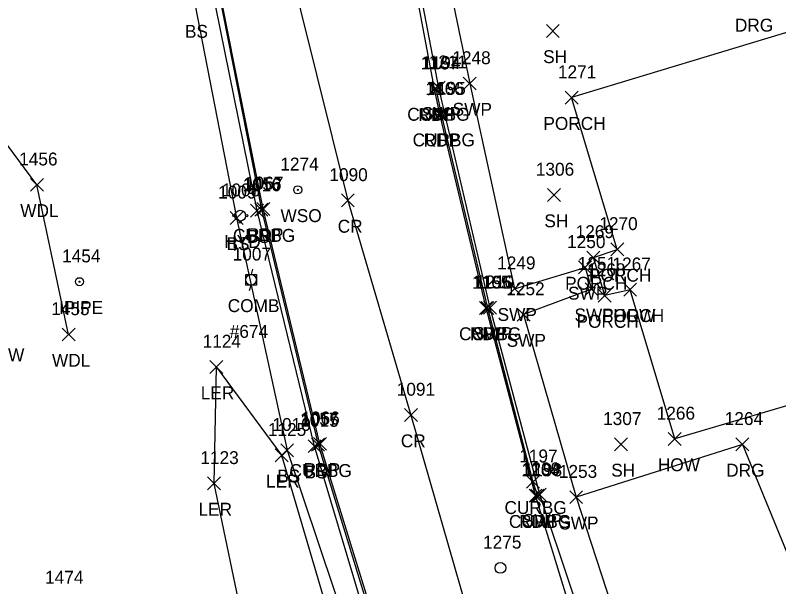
# Model space of a CAD drawing. Extents: x 462930 to 463548, y 29607 to 30453.
# Drawn here: x 463327.91 to 463364, y 30004.79 to 30031.8 of the extents above; entities that cross this region are included whole.
import ezdxf

# ---------------------------------------------------------------- set-up
doc = ezdxf.new("R2010")
doc.units = 0
for name, color, linetype in [('L_A', 7, 'Continuous'), ('L_I', 7, 'Continuous'), ('L_TIC', 7, 'Continuous'), ('LARO', 7, 'Continuous'), ('LAWA', 7, 'Continuous'), ('LBC', 7, 'Continuous'), ('LBF', 7, 'Continuous'), ('LELB', 7, 'Continuous'), ('M_A', 7, 'Continuous'), ('M_I', 7, 'Continuous'), ('MPIP', 7, 'Continuous'), ('P_A', 7, 'Continuous'), ('P_I', 7, 'Continuous'), ('P_TIC', 7, 'Continuous'), ('PET', 7, 'Continuous'), ('PRC', 7, 'Continuous'), ('R_A', 7, 'Continuous'), ('R_I', 7, 'Continuous'), ('R_TIC', 7, 'Continuous'), ('RC', 7, 'Continuous'), ('RDG', 7, 'Continuous'), ('RSW', 7, 'Continuous'), ('U_A', 7, 'Continuous'), ('U_C', 7, 'Continuous'), ('U_I', 7, 'Continuous'), ('UP', 7, 'Continuous'), ('UUMH', 7, 'Continuous'), ('UWFH', 7, 'Continuous'), ('UWV', 7, 'Continuous')]:
    doc.layers.add(name, color=color, linetype=linetype)

msp = doc.modelspace()

# ---------------------------------------------------------------- linework, layer by layer
at = {"layer": 'L_TIC'}
for points in [[(463353.022, 30030.753), (463353.632, 30031.363)], [(463353.632, 30030.753), (463353.022, 30031.363)], [(463353.908, 30027.599), (463354.518, 30028.209)], [(463354.518, 30027.599), (463353.908, 30028.209)], [(463328.628, 30023.48), (463329.238, 30024.09)], [(463329.238, 30023.48), (463328.628, 30024.09)], [(463353.078, 30022.996), (463353.688, 30023.606)], [(463353.688, 30022.996), (463353.078, 30023.606)], [(463339.039, 30022.26), (463339.649, 30022.87)], [(463339.649, 30022.26), (463339.039, 30022.87)], [(463338.068, 30021.915), (463338.678, 30022.525)], [(463338.678, 30021.915), (463338.068, 30022.525)], [(463356.064, 30020.426), (463356.674, 30021.036)], [(463356.674, 30020.426), (463356.064, 30021.036)], [(463354.935, 30020.045), (463355.545, 30020.655)], [(463355.545, 30020.045), (463354.935, 30020.655)], [(463356.675, 30018.519), (463357.285, 30019.129)], [(463357.285, 30018.519), (463356.675, 30019.129)], [(463356.675, 30018.519), (463357.285, 30019.129)], [(463357.285, 30018.519), (463356.675, 30019.129)], [(463355.473, 30018.246), (463356.083, 30018.856)], [(463356.083, 30018.246), (463355.473, 30018.856)], [(463330.127, 30016.406), (463330.737, 30017.016)], [(463330.737, 30016.406), (463330.127, 30017.016)], [(463337.112, 30014.868), (463337.722, 30015.478)], [(463337.722, 30014.868), (463337.112, 30015.478)], [(463341.758, 30011.13), (463342.368, 30011.74)], [(463342.368, 30011.13), (463341.758, 30011.74)], [(463356.241, 30011.213), (463356.851, 30011.823)], [(463356.851, 30011.213), (463356.241, 30011.823)], [(463358.781, 30011.469), (463359.391, 30012.079)], [(463359.391, 30011.469), (463358.781, 30012.079)], [(463340.462, 30010.935), (463341.072, 30011.545)], [(463341.072, 30010.935), (463340.462, 30011.545)], [(463340.197, 30010.697), (463340.807, 30011.307)], [(463340.807, 30010.697), (463340.197, 30011.307)], [(463337.004, 30009.368), (463337.614, 30009.978)], [(463337.614, 30009.368), (463337.004, 30009.978)]]:
    msp.add_lwpolyline(points, dxfattribs=at)
at = {"layer": 'LARO'}
msp.add_lwpolyline([(463338.843, 30002.341), (463337.309, 30009.673), (463337.417, 30015.173), (463340.502, 30011.002), (463343.497, 30000.853), (463342.386, 29996.619)], dxfattribs=at)
at = {"layer": 'LAWA'}
msp.add_lwpolyline([(463330.432, 30016.711), (463328.933, 30023.785), (463324.352, 30029.963), (463323.999, 30045.998), (463316.369, 30054.308), (463309.597, 30050.547)], dxfattribs=at)
at = {"layer": 'LBC'}
for points in [[(463364.851, 30031.129), (463354.213, 30027.904)], [(463359.086, 30011.774), (463356.98, 30018.824)], [(463369.71, 30014.92), (463359.086, 30011.774)]]:
    msp.add_lwpolyline(points, dxfattribs=at)
at = {"layer": 'LBF'}
msp.add_lwpolyline([(463356.98, 30018.824), (463355.778, 30018.551), (463355.24, 30020.35), (463356.369, 30020.731), (463354.213, 30027.904)], dxfattribs=at)
at = {"layer": 'LELB'}
for points in [[(463338.373, 30022.22), (463340.767, 30011.24), (463345.965, 29995.767), (463346.937, 29987.36), (463347.521, 29987.525), (463346.646, 29996.093), (463342.063, 30011.435), (463339.344, 30022.565), (463336.301, 30037.573), (463333.414, 30053.384), (463330.633, 30068.275), (463328.629, 30079.728), (463328.086, 30089.487), (463328.627, 30097.184), (463330.299, 30105.361), (463329.682, 30105.522), (463327.994, 30097.289)], [(463336.408, 30032.254), (463338.373, 30022.22)]]:
    msp.add_lwpolyline(points, dxfattribs=at)
at = {"layer": 'MPIP'}
for radius in [0.191, 0.0254]:
    msp.add_circle((463330.946, 30019.205), radius, dxfattribs=at)
at = {"layer": 'P_TIC'}
for points in [[(463347.428, 30028.015), (463348.038, 30028.625)], [(463348.038, 30028.015), (463347.428, 30028.625)], [(463347.675, 30026.81), (463348.285, 30027.42)], [(463348.285, 30026.81), (463347.675, 30027.42)], [(463343.327, 30022.74), (463343.937, 30023.35)], [(463343.937, 30022.74), (463343.327, 30023.35)], [(463339.328, 30022.341), (463339.938, 30022.951)], [(463339.938, 30022.341), (463339.328, 30022.951)], [(463349.862, 30017.661), (463350.472, 30018.271)], [(463350.472, 30017.661), (463349.862, 30018.271)], [(463346.312, 30012.599), (463346.922, 30013.209)], [(463346.922, 30012.599), (463346.312, 30013.209)], [(463342.009, 30011.241), (463342.619, 30011.851)], [(463342.619, 30011.241), (463342.009, 30011.851)], [(463352.2, 30008.793), (463352.81, 30009.403)], [(463352.81, 30008.793), (463352.2, 30009.403)]]:
    msp.add_lwpolyline(points, dxfattribs=at)
at = {"layer": 'PET'}
for points in [[(463374.338, 29956.391), (463367.555, 29969.533), (463365.556, 29974.625), (463364.583, 29976.896), (463356.695, 29995.475), (463352.505, 30009.098), (463350.167, 30017.966), (463347.98, 30027.115), (463347.733, 30028.32), (463346.051, 30037.294), (463343.907, 30048.483), (463342.761, 30054.643), (463342.551, 30055.85), (463341.301, 30062.483), (463338.432, 30077.399), (463338.227, 30078.623), (463337.48, 30086.968), (463337.479, 30088.196), (463338.474, 30099.226), (463339.751, 30104.374), (463341.961, 30110.783)], [(463349.052, 29990.82), (463346.99, 29996.409), (463342.314, 30011.546), (463339.633, 30022.646), (463336.631, 30037.644), (463333.669, 30053.397), (463330.887, 30068.339), (463328.89, 30079.76), (463328.357, 30089.522), (463328.892, 30097.183), (463330.561, 30105.3)]]:
    msp.add_lwpolyline(points, dxfattribs=at)
at = {"layer": 'PRC'}
msp.add_lwpolyline([(463337.978, 30112.385), (463335.087, 30099.771), (463333.576, 30084.385), (463334.686, 30068.796), (463337.03, 30053.748), (463339.908, 30038.01), (463343.632, 30023.045), (463346.617, 30012.904), (463351.044, 29997.524), (463354.76, 29987.177), (463360.584, 29974.202), (463367.548, 29960.534), (463374.695, 29948.349)], dxfattribs=at)
at = {"layer": 'R_TIC'}
for points in [[(463349.089, 30028.266), (463349.699, 30028.876)], [(463349.699, 30028.266), (463349.089, 30028.876)], [(463347.483, 30028.03), (463348.093, 30028.64)], [(463348.093, 30028.03), (463347.483, 30028.64)], [(463347.625, 30028.066), (463348.235, 30028.676)], [(463348.235, 30028.066), (463347.625, 30028.676)], [(463347.737, 30026.821), (463348.347, 30027.431)], [(463348.347, 30026.821), (463347.737, 30027.431)], [(463339.243, 30022.308), (463339.853, 30022.918)], [(463339.853, 30022.308), (463339.243, 30022.918)], [(463354.542, 30019.576), (463355.152, 30020.186)], [(463355.152, 30019.576), (463354.542, 30020.186)], [(463351.211, 30018.569), (463351.821, 30019.179)], [(463351.821, 30018.569), (463351.211, 30019.179)], [(463354.847, 30018.546), (463355.457, 30019.156)], [(463355.457, 30018.546), (463354.847, 30019.156)], [(463349.932, 30017.659), (463350.542, 30018.269)], [(463350.542, 30017.659), (463349.932, 30018.269)], [(463350.052, 30017.672), (463350.662, 30018.282)], [(463350.662, 30017.672), (463350.052, 30018.282)], [(463351.64, 30017.348), (463352.25, 30017.958)], [(463352.25, 30017.348), (463351.64, 30017.958)], [(463341.919, 30011.196), (463342.529, 30011.806)], [(463342.529, 30011.196), (463341.919, 30011.806)], [(463361.982, 30011.214), (463362.592, 30011.824)], [(463362.592, 30011.214), (463361.982, 30011.824)], [(463352.08, 30009.445), (463352.69, 30010.055)], [(463352.69, 30009.445), (463352.08, 30010.055)], [(463352.29, 30008.789), (463352.9, 30009.399)], [(463352.9, 30008.789), (463352.29, 30009.399)], [(463352.406, 30008.837), (463353.016, 30009.447)], [(463353.016, 30008.837), (463352.406, 30009.447)], [(463354.125, 30008.717), (463354.735, 30009.327)], [(463354.735, 30008.717), (463354.125, 30009.327)]]:
    msp.add_lwpolyline(points, dxfattribs=at)
at = {"layer": 'RC'}
for points in [[(463330.433, 30105.335), (463330.506, 30105.311), (463328.851, 30097.179), (463328.319, 30089.513), (463328.85, 30079.744), (463330.845, 30068.328), (463333.629, 30053.397), (463336.583, 30037.649), (463339.548, 30022.613), (463342.224, 30011.501), (463346.871, 29996.398), (463346.791, 29996.353)], [(463347.788, 30028.335), (463348.042, 30027.126), (463350.237, 30017.964), (463352.385, 30009.75), (463352.595, 30009.094)]]:
    msp.add_lwpolyline(points, dxfattribs=at)
at = {"layer": 'RDG'}
for points in [[(463362.287, 30011.519), (463354.43, 30009.022)], [(463362.287, 30011.519), (463366.742, 30000.689)]]:
    msp.add_lwpolyline(points, dxfattribs=at)
at = {"layer": 'RSW'}
for points in [[(463374.235, 29956.952), (463367.745, 29969.631), (463365.689, 29974.684), (463364.801, 29976.975), (463360.584, 29986.798), (463357.266, 29995.548), (463352.711, 30009.142), (463350.357, 30017.977), (463347.93, 30028.371), (463346.21, 30037.33), (463344.933, 30043.874), (463342.934, 30054.68), (463342.697, 30055.906), (463341.529, 30062.506)], [(463343.219, 30061.394), (463344.068, 30056.729), (463345.278, 30049.664), (463349.011, 30050.331), (463349.136, 30049.5), (463345.464, 30048.695), (463348.188, 30034.438), (463349.394, 30028.571), (463351.516, 30018.874), (463354.847, 30019.881), (463355.152, 30018.851), (463351.945, 30017.653), (463354.43, 30009.022), (463358.466, 29996.654), (463360.056, 29991.977), (463362.488, 29992.816), (463362.797, 29991.975), (463360.41, 29991.038), (463367.128, 29975.306), (463368.967, 29969.775), (463370.499, 29966.766)]]:
    msp.add_lwpolyline(points, dxfattribs=at)
at = {"layer": 'UP'}
for p, q in [((463339.133, 30019.801), (463339.057, 30019.547)), ((463338.803, 30019.039), (463338.803, 30019.547)), ((463338.803, 30019.547), (463339.311, 30019.547)), ((463339.311, 30019.547), (463339.311, 30019.039)), ((463339.311, 30019.039), (463338.803, 30019.039)), ((463338.981, 30018.785), (463339.057, 30019.039)), ((463339.057, 30019.293), (463339.057, 30019.293))]:
    msp.add_line(p, q, dxfattribs=at)
msp.add_circle((463339.057, 30019.293), 0.254, dxfattribs=at)
at = {"layer": 'UUMH'}
for p, q in [((463350.847, 30005.68), (463350.847, 30005.68)), ((463351.101, 30005.68), (463351.101, 30005.68))]:
    msp.add_line(p, q, dxfattribs=at)
msp.add_circle((463350.847, 30005.68), 0.254, dxfattribs=at)
at = {"layer": 'UWFH'}
msp.add_line((463338.547, 30022.325), (463338.547, 30022.325), dxfattribs=at)
for centre, radius in [((463338.547, 30022.325), 0.254), ((463338.242, 30022.325), 0.0508), ((463338.852, 30022.325), 0.0508), ((463338.547, 30022.02), 0.0508)]:
    msp.add_circle(centre, radius, dxfattribs=at)
at = {"layer": 'UWV'}
for radius in [0.191, 0.0254]:
    msp.add_circle((463341.264, 30023.546), radius, dxfattribs=at)

# ---------------------------------------------------------------- texts
at = {"layer": 'L_A'}
for s, p in [('BS', (463335.933, 30030.73)), ('SH', (463352.866, 30029.534)), ('PORCH', (463352.879, 30026.38)), ('WDL', (463328.146, 30022.261)), ('SH', (463352.922, 30021.777)), ('BS', (463338.869, 30021.041)), ('BS', (463337.898, 30020.696)), ('PORCH', (463355.035, 30019.207)), ('PORCH', (463353.906, 30018.826)), ('PORCH', (463355.646, 30017.3)), ('HOW', (463356.183, 30017.3)), ('PORCH', (463354.444, 30017.027)), ('WDL', (463329.645, 30015.187)), ('LER', (463336.68, 30013.649)), ('HOW', (463358.289, 30010.25)), ('BS', (463340.292, 30009.716)), ('BS', (463341.588, 30009.911)), ('SH', (463356.085, 30009.994)), ('LER', (463339.765, 30009.478)), ('LER', (463336.572, 30008.149))]:
    msp.add_text(s, height=0.6096, dxfattribs=at).set_placement(p)
at = {"layer": 'L_I'}
for s, p in [('1271', (463353.565, 30028.818)), ('1456', (463328.095, 30024.699)), ('1306', (463352.521, 30024.215)), ('1016', (463338.655, 30023.479)), ('1009', (463337.502, 30023.134)), ('1270', (463355.522, 30021.645)), ('1269', (463354.402, 30021.264)), ('1268', (463354.943, 30019.465)), ('1267', (463356.145, 30019.738)), ('1267', (463356.145, 30019.738)), ('1455', (463329.611, 30017.625)), ('1124', (463336.769, 30016.087)), ('1266', (463358.234, 30012.688)), ('1015', (463341.391, 30012.349)), ('1307', (463355.701, 30012.432)), ('1125', (463339.854, 30011.916)), ('1010', (463340.069, 30012.154)), ('1123', (463336.661, 30010.587)), ('1474', (463329.32, 30004.933))]:
    msp.add_text(s, height=0.6096, dxfattribs=at).set_placement(p)
at = {"layer": 'M_A'}
msp.add_text('IPIPE', height=0.6096, dxfattribs=at).set_placement((463329.981, 30017.681))
at = {"layer": 'M_I'}
msp.add_text('1454', height=0.6096, dxfattribs=at).set_placement((463330.125, 30020.119))
at = {"layer": 'P_A'}
for s, p in [('RDP', (463346.967, 30026.796)), ('RDP', (463347.214, 30025.591)), ('CR', (463343.154, 30021.521)), ('RDP', (463338.867, 30021.122)), ('RDP', (463349.401, 30016.442)), ('CR', (463346.139, 30011.38)), ('RDP', (463341.548, 30010.022)), ('RDP', (463351.739, 30007.574))]:
    msp.add_text(s, height=0.6096, dxfattribs=at).set_placement(p)
at = {"layer": 'P_I'}
for s, p in [('1167', (463347.071, 30029.234)), ('1166', (463347.301, 30028.029)), ('1090', (463342.761, 30023.959)), ('1067', (463338.774, 30023.56)), ('1165', (463349.505, 30018.88)), ('1091', (463345.945, 30013.818)), ('1066', (463341.438, 30012.46)), ('1164', (463351.843, 30010.012))]:
    msp.add_text(s, height=0.6096, dxfattribs=at).set_placement(p)
at = {"layer": 'R_A'}
for s, p in [('DRG', (463361.932, 30031.023)), ('SWP', (463348.59, 30027.047)), ('CURBG', (463346.442, 30026.811)), ('SWP', (463347.126, 30026.847)), ('CURBG', (463346.696, 30025.602)), ('CURBG', (463338.202, 30021.089)), ('SWP', (463354.043, 30018.357)), ('SWP', (463350.712, 30017.35)), ('SWP', (463354.348, 30017.327)), ('CURBG', (463348.891, 30016.44)), ('SWP', (463349.553, 30016.453)), ('SWP', (463351.141, 30016.129)), ('CURBG', (463340.878, 30009.977)), ('DRG', (463361.521, 30009.995)), ('CURBG', (463351.039, 30008.226)), ('CURBG', (463351.249, 30007.57)), ('SWP', (463351.907, 30007.618)), ('SWP', (463353.626, 30007.498))]:
    msp.add_text(s, height=0.6096, dxfattribs=at).set_placement(p)
at = {"layer": 'R_I'}
for s, p in [('1194', (463347.14, 30029.249)), ('1211', (463347.455, 30029.285)), ('1248', (463348.573, 30029.485)), ('1195', (463347.394, 30028.04)), ('1056', (463338.686, 30023.527)), ('1250', (463354, 30020.795)), ('1249', (463350.693, 30019.788)), ('1251', (463354.504, 30019.765)), ('1196', (463349.572, 30018.878)), ('1210', (463349.683, 30018.891)), ('1252', (463351.124, 30018.567)), ('1057', (463341.379, 30012.415)), ('1264', (463361.452, 30012.433)), ('1197', (463351.737, 30010.664)), ('1209', (463351.864, 30010.056)), ('1198', (463351.947, 30010.008)), ('1253', (463353.609, 30009.936))]:
    msp.add_text(s, height=0.6096, dxfattribs=at).set_placement(p)
at = {"layer": 'U_A'}
for s, p in [('WSO', (463340.45, 30022.022)), ('HYD', (463337.791, 30020.801)), ('COMB', (463337.955, 30017.769)), ('GUYW', (463325.804, 30015.441))]:
    msp.add_text(s, height=0.6096, dxfattribs=at).set_placement(p)
at = {"layer": 'U_C'}
msp.add_text('#674', height=0.6096, dxfattribs=at).set_placement((463338.049, 30016.55))
at = {"layer": 'U_I'}
for s, p in [('1274', (463340.443, 30024.46)), ('1008', (463337.678, 30023.239)), ('1007', (463338.188, 30020.207)), ('1275', (463350.026, 30006.594))]:
    msp.add_text(s, height=0.6096, dxfattribs=at).set_placement(p)

doc.saveas('drawing.dxf')
